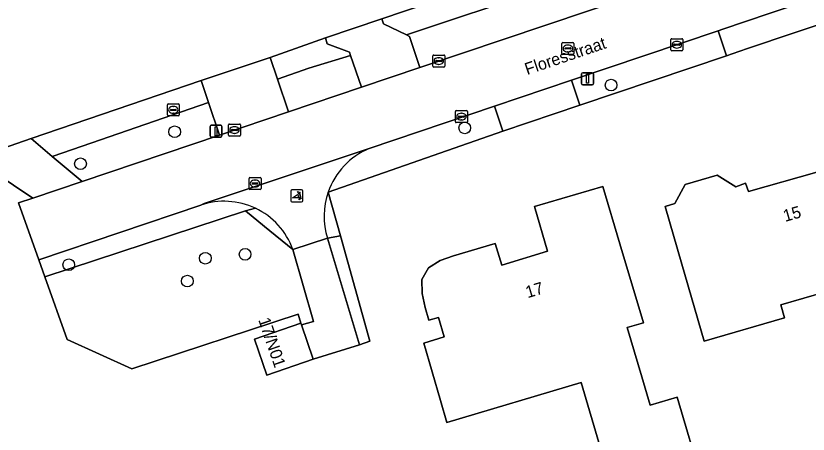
# Model space of a CAD drawing. Extents: x 162417 to 163722, y 384268 to 385417.
# Drawn here: x 163208.3 to 163274.6, y 384535.3 to 384570.3 of the extents above; entities that cross this region are included whole.
import ezdxf

# ---------------------------------------------------------------- set-up
doc = ezdxf.new("R2010")
doc.units = 0
for name, color, linetype in [('IMGEO_Berm_groen', 7, 'Continuous'), ('IMGEO_Boom', 7, 'Continuous'), ('IMGEO_Brandkraan', 7, 'Continuous'), ('IMGEO_Erf', 7, 'Continuous'), ('IMGEO_Groenvoorziening', 7, 'Continuous'), ('IMGEO_Hek', 7, 'Continuous'), ('IMGEO_Kolk', 7, 'Continuous'), ('IMGEO_Lichtmast', 7, 'Continuous'), ('IMGEO_Openbare_ruimte_label', 7, 'Continuous'), ('IMGEO_Pand', 7, 'Continuous'), ('IMGEO_Pand_nummerreeks', 7, 'Continuous'), ('IMGEO_Poller', 7, 'Continuous'), ('IMGEO_Rijbaan_lokaal_open', 7, 'Continuous'), ('IMGEO_Rioolput', 7, 'Continuous'), ('IMGEO_Voetpad_open', 7, 'Continuous')]:
    doc.layers.add(name, color=color, linetype=linetype)

msp = doc.modelspace()

# ---------------------------------------------------------------- linework, layer by layer
at = {"layer": 'IMGEO_Berm_groen'}
for points in [[(163273.724, 384576.587), (163272.82, 384579.284), (163269.253, 384578.101), (163266.372, 384577.12), (163248.058, 384571.028), (163245.191, 384570.072), (163243.67, 384569.568), (163240.996, 384568.674), (163241.264, 384568.545), (163242.124, 384565.946)], [(163236.319, 384566.969), (163232.841, 384565.895), (163230.205, 384564.99), (163231.127, 384562.247), (163237.23, 384564.298)], [(163225.376, 384560.307), (163224.462, 384563.018), (163213.887, 384559.385), (163211.389, 384558.534), (163213.881, 384556.436)]]:
    msp.add_lwpolyline(points, close=True, dxfattribs=at)
at = {"layer": 'IMGEO_Boom'}
for centre in [(163258.105, 384564.484), (163245.871, 384560.912), (163221.621, 384560.584), (163213.749, 384557.911), (163227.513, 384550.352), (163224.183, 384550.024), (163212.772, 384549.48), (163222.683, 384548.115)]:
    msp.add_circle(centre, 0.489, dxfattribs=at)
at = {"layer": 'IMGEO_Brandkraan'}
for p, q in [((163221.01, 384561.988), (163221.01, 384562.84)), ((163221.085, 384562.914), (163221.937, 384562.914)), ((163221.498, 384562.694), (163221.523, 384562.694)), ((163222.011, 384562.84), (163222.011, 384561.988)), ((163221.269, 384562.408), (163221.269, 384562.42)), ((163221.707, 384562.371), (163221.309, 384562.371)), ((163221.312, 384562.457), (163221.71, 384562.457)), ((163221.521, 384562.134), (163221.496, 384562.134)), ((163221.753, 384562.42), (163221.753, 384562.408)), ((163221.937, 384561.914), (163221.085, 384561.914))]:
    msp.add_line(p, q, dxfattribs=at)
for points in [[(163221.01, 384561.988), (163221.01, 384562.84)], [(163221.085, 384562.914), (163221.937, 384562.914)], [(163222.011, 384562.84), (163222.011, 384561.988)], [(163221.937, 384561.914), (163221.085, 384561.914)]]:
    msp.add_lwpolyline(points, dxfattribs=at)
for centre, radius, start, end in [((163221.087, 384562.838), 0.0765, 91.55205, 178.44795), ((163221.087, 384562.838), 0.0765, 91.55205, 178.44795), ((163221.935, 384562.838), 0.0765, 1.55205, 88.44795), ((163221.935, 384562.838), 0.0765, 1.55205, 88.44795), ((163221.309, 384562.417), 0.0403, 85.87752, 175.75265), ((163221.306, 384562.407), 0.0366, 178.93798, 274.71019), ((163221.71, 384562.414), 0.043, 264.86636, 352.45326), ((163221.714, 384562.419), 0.0386, 1.73085, 96.63898), ((163221.087, 384561.99), 0.0765, 181.55205, 268.44795), ((163221.087, 384561.99), 0.0765, 181.55205, 268.44795), ((163221.935, 384561.99), 0.0765, 271.55205, 358.44795), ((163221.935, 384561.99), 0.0765, 271.55205, 358.44795)]:
    msp.add_arc(centre, radius, start, end, dxfattribs=at)
for centre, major_axis, ratio, start_param, end_param in [((163221.497, 384562.414), (-0.387, 0.002), 0.722429, 4.712389, 7.853982), ((163221.522, 384562.414), (-0.39, 0.002), 0.717154, 1.570796, 4.712389)]:
    msp.add_ellipse(centre, major_axis=major_axis, ratio=ratio, start_param=start_param, end_param=end_param, dxfattribs=at)
at = {"layer": 'IMGEO_Erf'}
for points in [[(163281.221, 384571.476), (163269.519, 384567.53), (163268.22, 384567.092), (163267.748, 384566.933), (163255.498, 384562.802), (163249.052, 384560.628), (163234.458, 384555.553), (163235.475, 384551.907), (163237.934, 384543.097), (163237.073, 384542.789), (163233.205, 384541.59), (163229.331, 384540.268), (163228.305, 384543.274), (163232.179, 384544.596), (163231.94, 384545.348), (163218.051, 384540.791), (163212.642, 384543.23), (163210.775, 384548.469), (163210.271, 384549.883), (163208.571, 384554.648), (163209.757, 384555.048), (163204.802, 384558.366), (163209.626, 384560.018), (163223.841, 384564.861), (163229.598, 384566.797), (163234.231, 384568.441), (163238.95, 384570.032), (163272.155, 384581.269)], [(163278.073, 384547.795), (163272.306, 384546.119), (163272.616, 384545.055), (163265.9, 384543.103), (163264.032, 384549.53), (163262.637, 384554.331), (163263.444, 384554.587), (163264.311, 384556.17), (163266.977, 384556.956), (163268.545, 384555.984), (163269.343, 384556.279), (163269.597, 384555.592), (163275.314, 384557.224)], [(163260.326, 384523.665), (163255.591, 384539.64), (163244.387, 384536.315), (163243.849, 384538.144), (163242.439, 384542.94), (163244.155, 384543.45), (163243.671, 384545.079), (163242.88, 384544.845), (163242.568, 384545.921), (163242.307, 384547.074), (163242.283, 384548.234), (163242.833, 384549.209), (163243.826, 384549.835), (163244.928, 384550.233), (163248.419, 384551.262), (163248.969, 384549.45), (163252.794, 384550.611), (163251.709, 384554.331), (163257.427, 384556.023), (163258.848, 384551.23), (163260.806, 384544.628), (163259.464, 384544.23), (163260.686, 384540.108), (163261.383, 384537.757), (163263.629, 384538.423), (163267.82, 384524.286)]]:
    msp.add_lwpolyline(points, dxfattribs=at)
at = {"layer": 'IMGEO_Groenvoorziening'}
for points in [[(163267.748, 384566.933), (163267.045, 384569.018), (163254.795, 384564.887), (163255.498, 384562.802)], [(163232.229, 384544.448), (163233.229, 384544.738), (163231.501, 384550.761), (163229.132, 384552.684), (163227.531, 384553.984), (163210.775, 384548.469), (163212.642, 384543.23), (163218.051, 384540.791), (163231.94, 384545.348), (163232.179, 384544.596)], [(163235.475, 384551.907), (163234.398, 384551.697), (163237.073, 384542.789), (163237.934, 384543.097)]]:
    msp.add_lwpolyline(points, close=True, dxfattribs=at)
for points in [[(163234.458, 384555.553), (163249.052, 384560.628), (163248.354, 384562.715), (163237.892, 384559.187)], [(163234.398, 384551.697), (163235.475, 384551.907), (163234.458, 384555.553)], [(163223.8, 384554.456), (163210.271, 384549.883), (163210.775, 384548.469), (163227.531, 384553.984), (163228.373, 384554.195)], [(163228.373, 384554.195), (163227.531, 384553.984), (163229.132, 384552.684), (163231.501, 384550.761)]]:
    msp.add_lwpolyline(points, dxfattribs=at)
for centre, radius, start, end in [((163240.233, 384553.535), 6.118, 112.50252, 160.73916), ((163240.229, 384553.535), 6.114, 160.72392, 197.49316), ((163225.764, 384548.681), 6.1, 64.68256, 108.78431), ((163225.76, 384548.673), 6.109, 19.98609, 64.67413)]:
    msp.add_arc(centre, radius, start, end, dxfattribs=at)
at = {"layer": 'IMGEO_Hek'}
for points in [[(163234.458, 384555.553), (163235.475, 384551.907)], [(163210.775, 384548.469), (163227.531, 384553.984)], [(163227.531, 384553.984), (163229.132, 384552.684), (163231.501, 384550.761)], [(163231.501, 384550.761), (163234.398, 384551.697)], [(163234.398, 384551.697), (163235.475, 384551.907)], [(163235.475, 384551.907), (163237.934, 384543.097)], [(163210.271, 384549.883), (163210.775, 384548.469)], [(163210.775, 384548.469), (163212.642, 384543.23), (163218.051, 384540.791), (163231.94, 384545.348), (163232.179, 384544.596)], [(163237.073, 384542.789), (163237.934, 384543.097)]]:
    msp.add_lwpolyline(points, dxfattribs=at)
at = {"layer": 'IMGEO_Kolk'}
for p, q in [((163263.103, 384567.433), (163263.103, 384568.285)), ((163263.178, 384568.359), (163264.03, 384568.359)), ((163263.591, 384568.139), (163263.616, 384568.139)), ((163264.104, 384568.285), (163264.104, 384567.433)), ((163264.03, 384567.359), (163263.178, 384567.359)), ((163263.362, 384567.853), (163263.362, 384567.865)), ((163263.8, 384567.816), (163263.402, 384567.816)), ((163263.405, 384567.902), (163263.803, 384567.902)), ((163263.614, 384567.579), (163263.589, 384567.579)), ((163263.846, 384567.865), (163263.846, 384567.853)), ((163243.203, 384566.069), (163243.203, 384566.921)), ((163243.278, 384566.995), (163244.13, 384566.995)), ((163243.691, 384566.775), (163243.716, 384566.775)), ((163244.204, 384566.921), (163244.204, 384566.069)), ((163243.462, 384566.489), (163243.462, 384566.501)), ((163243.9, 384566.452), (163243.502, 384566.452)), ((163243.505, 384566.538), (163243.903, 384566.538)), ((163243.714, 384566.215), (163243.689, 384566.215)), ((163243.946, 384566.501), (163243.946, 384566.489)), ((163244.13, 384565.995), (163243.278, 384565.995)), ((163245.09, 384561.425), (163245.09, 384562.277)), ((163245.165, 384562.351), (163246.017, 384562.351)), ((163245.578, 384562.131), (163245.603, 384562.131)), ((163246.091, 384562.277), (163246.091, 384561.425)), ((163245.349, 384561.845), (163245.349, 384561.857)), ((163245.787, 384561.808), (163245.389, 384561.808)), ((163245.392, 384561.894), (163245.79, 384561.894)), ((163245.601, 384561.571), (163245.576, 384561.571)), ((163245.833, 384561.857), (163245.833, 384561.845)), ((163226.123, 384560.306), (163226.123, 384561.158)), ((163226.198, 384561.232), (163227.05, 384561.232)), ((163226.382, 384560.726), (163226.382, 384560.738)), ((163226.425, 384560.775), (163226.823, 384560.775)), ((163226.611, 384561.012), (163226.636, 384561.012)), ((163226.866, 384560.738), (163226.866, 384560.726)), ((163227.124, 384561.158), (163227.124, 384560.306)), ((163246.017, 384561.351), (163245.165, 384561.351)), ((163227.05, 384560.232), (163226.198, 384560.232)), ((163226.82, 384560.689), (163226.422, 384560.689)), ((163226.634, 384560.452), (163226.609, 384560.452)), ((163227.914, 384556.764), (163228.766, 384556.764)), ((163227.839, 384555.838), (163227.839, 384556.69)), ((163228.098, 384556.258), (163228.098, 384556.27)), ((163228.536, 384556.221), (163228.138, 384556.221)), ((163228.141, 384556.307), (163228.539, 384556.307)), ((163228.327, 384556.544), (163228.352, 384556.544)), ((163228.582, 384556.27), (163228.582, 384556.258)), ((163228.84, 384556.69), (163228.84, 384555.838)), ((163228.766, 384555.764), (163227.914, 384555.764)), ((163228.35, 384555.984), (163228.325, 384555.984))]:
    msp.add_line(p, q, dxfattribs=at)
for points in [[(163263.103, 384567.433), (163263.103, 384568.285)], [(163263.178, 384568.359), (163264.03, 384568.359)], [(163264.104, 384568.285), (163264.104, 384567.433)], [(163264.03, 384567.359), (163263.178, 384567.359)], [(163243.203, 384566.069), (163243.203, 384566.921)], [(163243.278, 384566.995), (163244.13, 384566.995)], [(163244.204, 384566.921), (163244.204, 384566.069)], [(163244.13, 384565.995), (163243.278, 384565.995)], [(163245.09, 384561.425), (163245.09, 384562.277)], [(163245.165, 384562.351), (163246.017, 384562.351)], [(163246.091, 384562.277), (163246.091, 384561.425)], [(163226.123, 384560.306), (163226.123, 384561.158)], [(163226.198, 384561.232), (163227.05, 384561.232)], [(163227.124, 384561.158), (163227.124, 384560.306)], [(163246.017, 384561.351), (163245.165, 384561.351)], [(163227.05, 384560.232), (163226.198, 384560.232)], [(163227.914, 384556.764), (163228.766, 384556.764)], [(163227.839, 384555.838), (163227.839, 384556.69)], [(163228.84, 384556.69), (163228.84, 384555.838)], [(163228.766, 384555.764), (163227.914, 384555.764)]]:
    msp.add_lwpolyline(points, dxfattribs=at)
for centre, radius, start, end in [((163263.18, 384568.283), 0.0765, 91.55205, 178.44795), ((163263.18, 384568.283), 0.0765, 91.55205, 178.44795), ((163264.028, 384568.283), 0.0765, 1.55205, 88.44795), ((163264.028, 384568.283), 0.0765, 1.55205, 88.44795), ((163263.18, 384567.435), 0.0765, 181.55205, 268.44795), ((163263.18, 384567.435), 0.0765, 181.55205, 268.44795), ((163263.402, 384567.862), 0.0403, 85.87752, 175.75265), ((163263.399, 384567.852), 0.0366, 178.93798, 274.71019), ((163263.803, 384567.859), 0.043, 264.86636, 352.45326), ((163263.807, 384567.864), 0.0386, 1.73085, 96.63898), ((163264.028, 384567.435), 0.0765, 271.55205, 358.44795), ((163264.028, 384567.435), 0.0765, 271.55205, 358.44795), ((163243.28, 384566.919), 0.0765, 91.55205, 178.44795), ((163243.28, 384566.919), 0.0765, 91.55205, 178.44795), ((163244.128, 384566.919), 0.0765, 1.55205, 88.44795), ((163244.128, 384566.919), 0.0765, 1.55205, 88.44795), ((163243.28, 384566.071), 0.0765, 181.55205, 268.44795), ((163243.28, 384566.071), 0.0765, 181.55205, 268.44795), ((163243.502, 384566.498), 0.0403, 85.87752, 175.75265), ((163243.499, 384566.488), 0.0366, 178.93798, 274.71019), ((163243.903, 384566.495), 0.043, 264.86636, 352.45326), ((163243.907, 384566.5), 0.0386, 1.73085, 96.63898), ((163244.128, 384566.071), 0.0765, 271.55205, 358.44795), ((163244.128, 384566.071), 0.0765, 271.55205, 358.44795), ((163245.167, 384562.275), 0.0765, 91.55205, 178.44795), ((163245.167, 384562.275), 0.0765, 91.55205, 178.44795), ((163246.015, 384562.275), 0.0765, 1.55205, 88.44795), ((163246.015, 384562.275), 0.0765, 1.55205, 88.44795), ((163245.167, 384561.427), 0.0765, 181.55205, 268.44795), ((163245.167, 384561.427), 0.0765, 181.55205, 268.44795), ((163245.389, 384561.854), 0.0403, 85.87752, 175.75265), ((163245.386, 384561.844), 0.0366, 178.93798, 274.71019), ((163245.79, 384561.851), 0.043, 264.86636, 352.45326), ((163245.794, 384561.856), 0.0386, 1.73085, 96.63898), ((163246.015, 384561.427), 0.0765, 271.55205, 358.44795), ((163246.015, 384561.427), 0.0765, 271.55205, 358.44795), ((163226.2, 384561.156), 0.0765, 91.55205, 178.44795), ((163226.2, 384561.156), 0.0765, 91.55205, 178.44795), ((163226.422, 384560.735), 0.0403, 85.87752, 175.75265), ((163226.419, 384560.725), 0.0366, 178.93798, 274.71019), ((163226.823, 384560.732), 0.043, 264.86636, 352.45326), ((163226.827, 384560.737), 0.0386, 1.73085, 96.63898), ((163227.048, 384561.156), 0.0765, 1.55205, 88.44795), ((163227.048, 384561.156), 0.0765, 1.55205, 88.44795), ((163226.2, 384560.308), 0.0765, 181.55205, 268.44795), ((163226.2, 384560.308), 0.0765, 181.55205, 268.44795), ((163227.048, 384560.308), 0.0765, 271.55205, 358.44795), ((163227.048, 384560.308), 0.0765, 271.55205, 358.44795), ((163227.916, 384556.688), 0.0765, 91.55205, 178.44795), ((163227.916, 384556.688), 0.0765, 91.55205, 178.44795), ((163228.764, 384556.688), 0.0765, 1.55205, 88.44795), ((163228.764, 384556.688), 0.0765, 1.55205, 88.44795), ((163228.138, 384556.267), 0.0403, 85.87752, 175.75265), ((163228.135, 384556.257), 0.0366, 178.93798, 274.71019), ((163228.539, 384556.264), 0.043, 264.86636, 352.45326), ((163228.543, 384556.269), 0.0386, 1.73085, 96.63898), ((163227.916, 384555.84), 0.0765, 181.55205, 268.44795), ((163227.916, 384555.84), 0.0765, 181.55205, 268.44795), ((163228.764, 384555.84), 0.0765, 271.55205, 358.44795), ((163228.764, 384555.84), 0.0765, 271.55205, 358.44795)]:
    msp.add_arc(centre, radius, start, end, dxfattribs=at)
for centre, major_axis, ratio, start_param, end_param in [((163263.59, 384567.859), (-0.387, 0.002), 0.722429, 4.712389, 7.853982), ((163263.615, 384567.859), (-0.39, 0.002), 0.717154, 1.570796, 4.712389), ((163243.69, 384566.495), (-0.387, 0.002), 0.722429, 4.712389, 7.853982), ((163243.715, 384566.495), (-0.39, 0.002), 0.717154, 1.570796, 4.712389), ((163245.577, 384561.851), (-0.387, 0.002), 0.722429, 4.712389, 7.853982), ((163245.602, 384561.851), (-0.39, 0.002), 0.717154, 1.570796, 4.712389), ((163226.61, 384560.732), (-0.387, 0.002), 0.722429, 4.712389, 7.853982), ((163226.635, 384560.732), (-0.39, 0.002), 0.717154, 1.570796, 4.712389), ((163228.326, 384556.264), (-0.387, 0.002), 0.722429, 4.712389, 7.853982), ((163228.351, 384556.264), (-0.39, 0.002), 0.717154, 1.570796, 4.712389)]:
    msp.add_ellipse(centre, major_axis=major_axis, ratio=ratio, start_param=start_param, end_param=end_param, dxfattribs=at)
at = {"layer": 'IMGEO_Lichtmast'}
for p, q in [((163255.641, 384564.613), (163255.641, 384565.413)), ((163255.641, 384565.413), (163255.641, 384564.613)), ((163255.741, 384565.513), (163256.531, 384565.513)), ((163256.531, 384565.513), (163255.741, 384565.513)), ((163256.631, 384565.413), (163256.631, 384564.613)), ((163256.631, 384564.613), (163256.631, 384565.413)), ((163256.531, 384564.513), (163255.741, 384564.513)), ((163255.741, 384564.513), (163256.531, 384564.513)), ((163224.581, 384560.234), (163224.581, 384561.034)), ((163224.581, 384561.034), (163224.581, 384560.234)), ((163224.681, 384561.134), (163225.471, 384561.134)), ((163225.471, 384561.134), (163224.681, 384561.134)), ((163225.571, 384561.034), (163225.571, 384560.234)), ((163225.571, 384560.234), (163225.571, 384561.034)), ((163225.471, 384560.134), (163224.681, 384560.134)), ((163224.681, 384560.134), (163225.471, 384560.134))]:
    msp.add_line(p, q, dxfattribs=at)
for points in [[(163256.061, 384565.388), (163256.211, 384565.388), (163256.211, 384564.638), (163256.061, 384564.638), (163256.061, 384565.388)], [(163225.001, 384561.009), (163225.151, 384561.009), (163225.151, 384560.259), (163225.001, 384560.259), (163225.001, 384561.009)]]:
    msp.add_lwpolyline(points, dxfattribs=at)
for centre, start, end in [((163255.741, 384565.413), 90, 180), ((163255.741, 384565.413), 90, 180), ((163256.531, 384565.413), 0, 90), ((163256.531, 384565.413), 360, 90), ((163255.741, 384564.613), 180, 270), ((163255.741, 384564.613), 180, 270), ((163256.531, 384564.613), 270, 0), ((163256.531, 384564.613), 270, 0), ((163224.681, 384561.034), 90, 180), ((163224.681, 384561.034), 90, 180), ((163225.471, 384561.034), 0, 90), ((163225.471, 384561.034), 360, 90), ((163224.681, 384560.234), 180, 270), ((163224.681, 384560.234), 180, 270), ((163225.471, 384560.234), 270, 0), ((163225.471, 384560.234), 270, 0)]:
    msp.add_arc(centre, 0.1, start, end, dxfattribs=at)
at = {"layer": 'IMGEO_Pand'}
for points in [[(163275.314, 384557.224), (163269.597, 384555.592), (163269.343, 384556.279), (163268.545, 384555.984), (163266.977, 384556.956), (163264.311, 384556.17), (163263.444, 384554.587), (163262.637, 384554.331), (163264.032, 384549.53), (163265.9, 384543.103), (163272.616, 384545.055), (163272.306, 384546.119), (163278.073, 384547.795)], [(163267.82, 384524.286), (163263.629, 384538.423), (163261.383, 384537.757), (163260.686, 384540.108), (163259.464, 384544.23), (163260.806, 384544.628), (163258.848, 384551.23), (163257.427, 384556.023), (163251.709, 384554.331), (163252.794, 384550.611), (163248.969, 384549.45), (163248.419, 384551.262), (163244.928, 384550.233), (163243.826, 384549.835), (163242.833, 384549.209), (163242.283, 384548.234), (163242.307, 384547.074), (163242.568, 384545.921), (163242.88, 384544.845), (163243.671, 384545.079), (163244.155, 384543.45), (163242.439, 384542.94), (163243.849, 384538.144), (163244.387, 384536.315), (163255.591, 384539.64), (163260.326, 384523.665)]]:
    msp.add_lwpolyline(points, dxfattribs=at)
msp.add_lwpolyline([(163233.205, 384541.59), (163232.229, 384544.448), (163232.179, 384544.596), (163228.305, 384543.274), (163229.331, 384540.268)], close=True, dxfattribs=at)
at = {"layer": 'IMGEO_Poller'}
for p, q in [((163231.337, 384555.629), (163231.337, 384554.822)), ((163231.337, 384555.629), (163231.337, 384554.822)), ((163232.239, 384555.724), (163231.431, 384555.724)), ((163232.239, 384555.724), (163231.431, 384555.724)), ((163232.333, 384554.822), (163232.333, 384555.629)), ((163232.333, 384554.822), (163232.333, 384555.629)), ((163231.431, 384554.727), (163232.239, 384554.727)), ((163231.431, 384554.727), (163232.239, 384554.727))]:
    msp.add_line(p, q, dxfattribs=at)
for points in [[(163232.016, 384555.453), (163232.004, 384555.38), (163231.879, 384555.585)], [(163231.879, 384555.585), (163232.11, 384555.519), (163232.039, 384555.487)], [(163231.972, 384555.08), (163231.459, 384555.08), (163231.889, 384555.355)], [(163232.032, 384554.908), (163232.098, 384555.139), (163232.128, 384555.071)], [(163232.164, 384555.044), (163232.236, 384555.033), (163232.032, 384554.908)]]:
    msp.add_lwpolyline(points, dxfattribs=at)
for centre, radius, start, end in [((163231.431, 384555.629), 0.0946, 90, 180), ((163231.431, 384555.629), 0.0946, 90, 180), ((163231.658, 384555.14), 0.476, 351.75274, 41.16905), ((163231.658, 384555.14), 0.516, 349.35686, 42.29123), ((163232.239, 384555.629), 0.0946, 0, 90), ((163232.239, 384555.629), 0.0946, 0, 90), ((163231.431, 384554.822), 0.0946, 180, 270), ((163231.431, 384554.822), 0.0946, 180, 270), ((163231.644, 384555.13), 0.332, 351.32473, 42.4854), ((163232.239, 384554.822), 0.0946, 270, 0), ((163232.239, 384554.822), 0.0946, 270, 0)]:
    msp.add_arc(centre, radius, start, end, dxfattribs=at)
at = {"layer": 'IMGEO_Rijbaan_lokaal_open'}
for points in [[(163277.613, 384577.896), (163273.724, 384576.587), (163242.124, 384565.946), (163237.23, 384564.298), (163231.127, 384562.247), (163225.376, 384560.307), (163213.881, 384556.436), (163209.757, 384555.048), (163208.571, 384554.648), (163210.271, 384549.883), (163223.8, 384554.456), (163224.099, 384554.581), (163237.892, 384559.187), (163248.354, 384562.715), (163254.795, 384564.887), (163267.045, 384569.018), (163267.446, 384569.153), (163271.31, 384570.456), (163280.541, 384573.569)], [(163237.892, 384559.187), (163224.099, 384554.581), (163223.8, 384554.456)], [(163231.501, 384550.761), (163234.398, 384551.697)]]:
    msp.add_lwpolyline(points, dxfattribs=at)
msp.add_lwpolyline([(163232.229, 384544.448), (163233.205, 384541.59), (163237.073, 384542.789), (163234.398, 384551.697), (163231.501, 384550.761), (163233.229, 384544.738)], close=True, dxfattribs=at)
for centre, radius, start, end in [((163240.233, 384553.535), 6.118, 112.50252, 160.73916), ((163240.229, 384553.535), 6.114, 160.72392, 197.49316), ((163225.764, 384548.681), 6.1, 64.68256, 108.78431), ((163225.76, 384548.673), 6.109, 19.98609, 64.67413)]:
    msp.add_arc(centre, radius, start, end, dxfattribs=at)
at = {"layer": 'IMGEO_Rioolput'}
for p, q in [((163254.065, 384568.042), (163254.917, 384568.042)), ((163253.99, 384567.116), (163253.99, 384567.968)), ((163254.249, 384567.536), (163254.249, 384567.548)), ((163254.687, 384567.499), (163254.289, 384567.499)), ((163254.292, 384567.585), (163254.69, 384567.585)), ((163254.478, 384567.822), (163254.503, 384567.822)), ((163254.733, 384567.548), (163254.733, 384567.536)), ((163254.991, 384567.968), (163254.991, 384567.116)), ((163254.917, 384567.042), (163254.065, 384567.042)), ((163254.501, 384567.262), (163254.476, 384567.262))]:
    msp.add_line(p, q, dxfattribs=at)
for points in [[(163254.065, 384568.042), (163254.917, 384568.042)], [(163253.99, 384567.116), (163253.99, 384567.968)], [(163254.991, 384567.968), (163254.991, 384567.116)], [(163254.917, 384567.042), (163254.065, 384567.042)]]:
    msp.add_lwpolyline(points, dxfattribs=at)
for centre, radius, start, end in [((163254.067, 384567.966), 0.0765, 91.55205, 178.44795), ((163254.067, 384567.966), 0.0765, 91.55205, 178.44795), ((163254.915, 384567.966), 0.0765, 1.55205, 88.44795), ((163254.915, 384567.966), 0.0765, 1.55205, 88.44795), ((163254.289, 384567.545), 0.0403, 85.87752, 175.75265), ((163254.286, 384567.535), 0.0366, 178.93798, 274.71019), ((163254.69, 384567.542), 0.043, 264.86636, 352.45326), ((163254.694, 384567.547), 0.0386, 1.73085, 96.63898), ((163254.067, 384567.118), 0.0765, 181.55205, 268.44795), ((163254.067, 384567.118), 0.0765, 181.55205, 268.44795), ((163254.915, 384567.118), 0.0765, 271.55205, 358.44795), ((163254.915, 384567.118), 0.0765, 271.55205, 358.44795)]:
    msp.add_arc(centre, radius, start, end, dxfattribs=at)
for centre, major_axis, ratio, start_param, end_param in [((163254.477, 384567.542), (-0.387, 0.002), 0.722429, 4.712389, 7.853982), ((163254.502, 384567.542), (-0.39, 0.002), 0.717154, 1.570796, 4.712389)]:
    msp.add_ellipse(centre, major_axis=major_axis, ratio=ratio, start_param=start_param, end_param=end_param, dxfattribs=at)
at = {"layer": 'IMGEO_Voetpad_open'}
for points in [[(163245.191, 384570.072), (163248.058, 384571.028), (163266.372, 384577.12), (163269.253, 384578.101), (163272.82, 384579.284), (163272.155, 384581.269), (163238.95, 384570.032), (163239.089, 384569.593), (163240.996, 384568.674), (163243.67, 384569.568)], [(163281.221, 384571.476), (163280.541, 384573.569), (163271.31, 384570.456), (163267.446, 384569.153), (163267.045, 384569.018), (163267.748, 384566.933), (163268.22, 384567.092), (163269.519, 384567.53)], [(163236.319, 384566.969), (163237.23, 384564.298), (163242.124, 384565.946), (163241.264, 384568.545), (163240.996, 384568.674), (163239.089, 384569.593), (163238.95, 384570.032), (163234.231, 384568.441), (163234.377, 384567.942), (163236.23, 384567.231)], [(163229.598, 384566.797), (163230.205, 384564.99), (163232.841, 384565.895), (163236.319, 384566.969), (163236.23, 384567.231), (163234.377, 384567.942), (163234.231, 384568.441)], [(163225.376, 384560.307), (163231.127, 384562.247), (163230.205, 384564.99), (163229.598, 384566.797), (163223.841, 384564.861), (163224.462, 384563.018)], [(163223.841, 384564.861), (163209.626, 384560.018), (163211.389, 384558.534), (163213.887, 384559.385), (163224.462, 384563.018)], [(163248.354, 384562.715), (163249.052, 384560.628), (163255.498, 384562.802), (163254.795, 384564.887)], [(163211.389, 384558.534), (163209.626, 384560.018), (163204.802, 384558.366), (163209.757, 384555.048), (163213.881, 384556.436)]]:
    msp.add_lwpolyline(points, close=True, dxfattribs=at)

# ---------------------------------------------------------------- texts
at = {"layer": 'IMGEO_Openbare_ruimte_label'}
msp.add_text('Floresstraat', height=1, rotation=18.72487, dxfattribs=at).set_placement((163251.086, 384565.317))
at = {"layer": 'IMGEO_Pand_nummerreeks'}
for s, rotation, p in [('15', 15.93396, (163272.649, 384553.052)), ('17', 16.88507, (163251.131, 384546.68)), ('17/N01', 288.87455, (163228.601, 384544.878))]:
    msp.add_text(s, height=1, rotation=rotation, dxfattribs=at).set_placement(p)

doc.saveas('drawing.dxf')
